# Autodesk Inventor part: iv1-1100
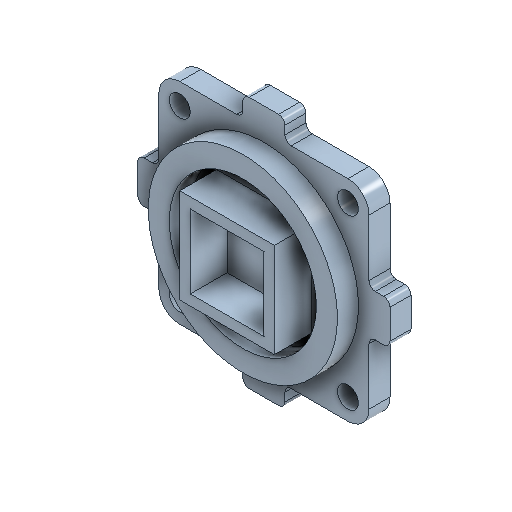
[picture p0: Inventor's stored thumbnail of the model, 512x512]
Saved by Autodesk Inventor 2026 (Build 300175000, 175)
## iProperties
Created: 2022-01
Part Number: iv1-1100
Material: Steel, Mild
Document SubType Name: Modeling
Designer: Lars Bertram Pedersen
Density: 7.85 g/cm^3
Appearance: Steel Blue
Author: Lars Bertram Pedersen
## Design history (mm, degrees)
sketch "Sketch2"
  geometry: L1 (-80, 100)-(-26, 100); L2 (-20, 106)-(-20, 114); L3 (-14, 120)-(14, 120); L4 (20, 114)-(20, 106); L5 (26, 100)-(80, 100); L6 (100, 80)-(100, 26); L7 (106, 20)-(114, 20); L8 (120, 14)-(120, -14); L9 (114, -20)-(106, -20); L10 (100, -26)-(100, -80); L11 (-100, 80)-(-100, 26); L12 (-106, 20)-(-114, 20); L13 (-120, 14)-(-120, -14); L14 (-114, -20)-(-106, -20); L15 (-100, -26)-(-100, -80); L16 (-80, -100)-(-26, -100); L17 (-20, -106)-(-20, -114); L18 (-14, -120)-(14, -120); L19 (20, -114)-(20, -106); L20 (26, -100)-(80, -100); C1 r 10 at (-80, 80); C2 r 10 at (80, 80); C3 r 10 at (80, -80); C4 r 10 at (-80, -80); A1 r 20 centre (-80, 80) between (-80, 100) and (-100, 80); A2 r 20 centre (80, 80) between (100, 80) and (80, 100); A3 r 20 centre (80, -80) between (80, -100) and (100, -80); A4 r 20 centre (-80, -80) between (-100, -80) and (-80, -100); A5 r 6 centre (-26, 106) between (-26, 100) and (-20, 106); A6 r 6 centre (-14, 114) between (-14, 120) and (-20, 114); A7 r 6 centre (14, 114) between (20, 114) and (14, 120); A8 r 6 centre (26, 106) between (20, 106) and (26, 100); A9 r 6 centre (106, 26) between (100, 26) and (106, 20); A10 r 6 centre (114, 14) between (120, 14) and (114, 20); A11 r 6 centre (114, -14) between (114, -20) and (120, -14); A12 r 6 centre (106, -26) between (106, -20) and (100, -26); A13 r 6 centre (26, -106) between (26, -100) and (20, -106); A14 r 6 centre (14, -114) between (14, -120) and (20, -114); A15 r 6 centre (-14, -114) between (-20, -114) and (-14, -120); A16 r 6 centre (-26, -106) between (-20, -106) and (-26, -100); A17 r 6 centre (-106, -26) between (-100, -26) and (-106, -20); A18 r 6 centre (-114, -14) between (-120, -14) and (-114, -20); A19 r 6 centre (-114, 14) between (-114, 20) and (-120, 14); A20 r 6 centre (-106, 26) between (-106, 20) and (-100, 26); 23 further points
  constraints: 45 point on line, 40 end point, 40 point on circle, 40 tangent, 24 centre point, 21 equal radius, 17 perpendicular, 5 coincident, 1 horizontal, 1 vertical
  dimensions: "d15" = 20 radius of A1 (derived); "d16" = 6 radius of A5; "d17" = 20 diameter of C1
extrude "Extrusion1" new body sketch "Sketch2" distance "d5" = 20 (= d17); taper "d6" = 0 deg
sketch "Sketch3"
  geometry: C1 r 70 at (0, 0); C2 r 90 at (0, 0); 1 further point
  constraints: 2 centre point, 2 coincident
  dimensions: "d7" = 180 diameter of C2; "d8" = 140 diameter of C1
extrude "Extrusion2" join sketch "Sketch3" distance "d9" = 20; taper "d10" = 0 deg
sketch "Sketch4"
  geometry: L1 (-35, -35)-(35, -35); L2 (35, -35)-(35, 35); L3 (35, 35)-(-35, 35); L4 (-35, 35)-(-35, -35); L5 (-35, -35)-(35, 35); L6 (35, -35)-(-35, 35); L7 (-45, -45)-(45, -45); L8 (45, -45)-(45, 45); L9 (45, 45)-(-45, 45); L10 (-45, 45)-(-45, -45); L11 (-45, -45)-(45, 45); L12 (45, -45)-(-45, 45); 1 further point
  constraints: 24 end point, 4 midpoint, 4 parallel, 3 perpendicular, 2 horizontal, 1 point on line
  dimensions: "d11" = 90 distance between parallel lines of L7 L9; "d12" = 70 distance of L1.end L2.end
extrude "Extrusion3" join sketch "Sketch4" distance "d13" = 35; taper "d14" = 0 deg
body "Solid1"
sketch "Sketch1"
  geometry: L1 (-100, -100)-(100, -100); L2 (100, -100)-(100, 100); L3 (100, 100)-(-100, 100); L4 (-100, 100)-(-100, -100); L5 (-100, -100)-(100, 100); L6 (100, -100)-(-100, 100); L7 (20, -120)-(-20, -120); L8 (-20, -120)-(-20, 120); L9 (-20, 120)-(20, 120); L10 (20, 120)-(20, -120); L11 (20, -120)-(-20, 120); L12 (-20, -120)-(20, 120); L13 (-120, 20)-(120, 20); L14 (120, 20)-(120, -20); L15 (120, -20)-(-120, -20); L16 (-120, -20)-(-120, 20); L17 (-120, 20)-(120, -20); L18 (120, 20)-(-120, -20); 1 further point
  constraints: 36 end point, 6 midpoint, 6 parallel, 4 perpendicular, 3 horizontal
  dimensions: "d0" = 200 distance of L2.end L3.end; "d1" = 20 distance between parallel lines of L3 L9; "d2" = 40 distance between parallel lines of L10 L8; "d3" = 40 distance of L13.end L14.end; "d4" = 20 distance between parallel lines of L14 L2
